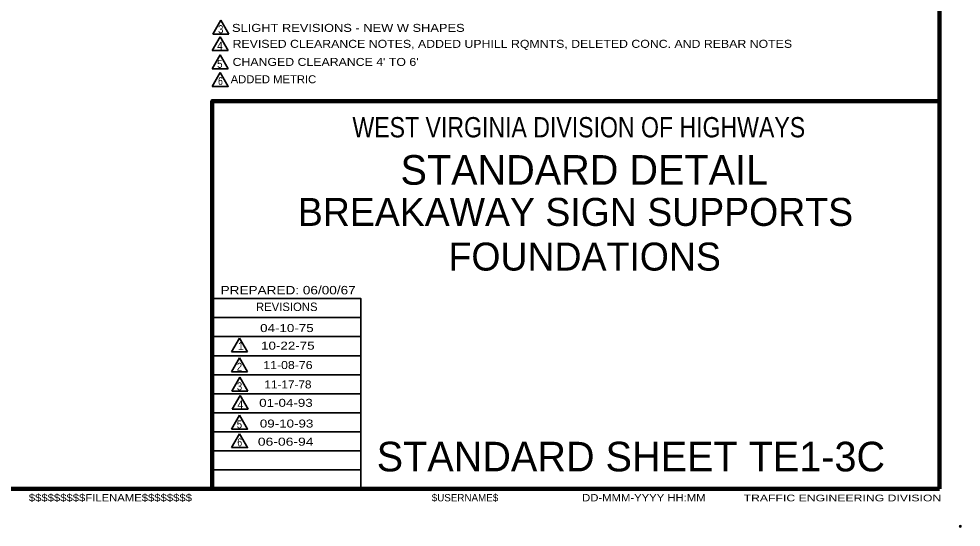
# Model space of a CAD drawing. Extents: x -27 to 828, y -12 to 532.
# Drawn here: x 546 to 828.5, y -12.5 to 140 of the extents above; entities that cross this region are included whole.
import ezdxf
from ezdxf.enums import TextEntityAlignment as Align

# ---------------------------------------------------------------- set-up
doc = ezdxf.new("R2010")
doc.units = 0
doc.header["$LTSCALE"] = 0.96
doc.header["$PDMODE"] = 32
doc.header["$PDSIZE"] = 0.48
doc.layers.add('1', color=7, linetype='Continuous', lineweight=35)
doc.layers.add('61', color=7, linetype='Continuous', lineweight=35)

msp = doc.modelspace()

# ---------------------------------------------------------------- linework, layer by layer
at = {"layer": '1', "lineweight": 158}
for q in [(821.9567, 525.1688), (821.9567, 115.3688), (30.3567, -0.9312)]:
    msp.add_line((821.9567, -0.9312), q, dxfattribs=at)
at = {"layer": '1', "lineweight": 13}
msp.add_line((821.9567, -0.9312), (821.9567, 525.1688), dxfattribs=at)
at = {"layer": '1'}
for p, q in [((606.5687, 139.616), (604.1687, 135.4591)), ((606.5687, 139.616), (608.9687, 135.4591)), ((606.2927, 134.647), (603.8927, 130.4901)), ((608.9687, 135.4591), (604.1687, 135.4591)), ((606.2927, 134.647), (608.6927, 130.4901)), ((608.6927, 130.4901), (603.8927, 130.4901)), ((606.2927, 129.2165), (603.8927, 125.0596)), ((606.2927, 129.2165), (608.6927, 125.0596)), ((608.6927, 125.0596), (603.8927, 125.0596)), ((606.375, 123.9367), (603.975, 119.7798)), ((648.4567, 50.4688), (603.9567, 50.4688)), ((648.4567, 44.7688), (603.9567, 44.7688)), ((612.1272, 44.2559), (609.7272, 40.099)), ((612.1272, 44.2559), (614.5272, 40.099)), ((614.5272, 40.099), (609.7272, 40.099)), ((648.4567, 38.9688), (603.9567, 38.9688)), ((612.1359, 38.2862), (609.7359, 34.1293)), ((612.1359, 38.2862), (614.5359, 34.1293)), ((614.5359, 34.1293), (609.7359, 34.1293)), ((648.4567, 33.2688), (603.9567, 33.2688)), ((612.1817, 32.5223), (609.7817, 28.3654)), ((612.1817, 32.5223), (614.5817, 28.3654)), ((614.5817, 28.3654), (609.7817, 28.3654)), ((648.4567, 27.5688), (603.9567, 27.5688)), ((612.3714, 27.0673), (609.9714, 22.9104)), ((612.3714, 27.0673), (614.7714, 22.9104)), ((614.7714, 22.9104), (609.9714, 22.9104)), ((648.4567, 21.8688), (603.9567, 21.8688)), ((612.1536, 21.107), (609.7536, 16.9501)), ((648.4567, 16.1688), (603.9567, 16.1688)), ((612.158, 15.5394), (609.758, 11.3825)), ((648.4567, 10.4688), (603.9567, 10.4688)), ((648.4567, 4.7688), (603.9567, 4.7688))]:
    msp.add_line(p, q, dxfattribs=at)
for points in [[(606.375, 123.9367), (608.775, 119.7798), (603.975, 119.7798)], [(648.4567, -0.9312), (648.4567, 56.1688), (603.9567, 56.1688)], [(612.1536, 21.107), (614.5536, 16.9501), (609.7536, 16.9501)], [(612.158, 15.5394), (614.558, 11.3825), (609.758, 11.3825)]]:
    msp.add_lwpolyline(points, dxfattribs=at)
at = {"layer": '1', "lineweight": 158}
msp.add_lwpolyline([(603.9567, -0.9312), (603.9567, 115.3688), (821.9567, 115.3688)], dxfattribs=at)
at = {"layer": '1'}
msp.add_point((828.2567, -12.2312), dxfattribs=at)
at = {"layer": '61', "lineweight": 53}
for q in [(669.2567, -0.9312), (669.2567, -0.9312), (669.2567, -0.9312), (669.5567, -0.9312), (669.5567, -0.9312)]:
    msp.add_line((821.9567, -0.9312), q, dxfattribs=at)

# ---------------------------------------------------------------- texts
at = {"layer": '1'}
for s, height, width, p in [('SLIGHT REVISIONS - NEW W SHAPES', 2.4, 1.2, (609.869, 136.1179)), ('3', 2.4, 0.9, (605.6919, 135.7262)), ('4', 2.4, 0.95, (605.4159, 130.7572)), ('REVISED CLEARANCE NOTES, ADDED UPHILL RQMNTS, DELETED CONC. AND REBAR NOTES', 2.4, 1.15, (610.053, 131.3329)), ('5', 2.4, 0.9, (605.4159, 125.3267)), ("CHANGED CLEARANCE 4' TO 6'", 2.4, 1.15, (610.053, 125.9024)), ('6', 2.4, 0.8, (605.6938, 120.1803)), ('ADDED METRIC', 2.4, 1.05, (609.4783, 120.7023)), ('PREPARED: 06/00/67', 2.537, 1.2, (606.4567, 57.3688)), ('2', 2.4, 0.9, (611.3114, 34.4598)), ('3', 2.4, 0.9, (611.3342, 28.5961)), ('4', 2.4, 0.95, (611.5239, 23.1411)), ('5', 2.4, 0.9, (611.3061, 17.1808)), ('6', 2.4, 0.8, (611.4768, 11.783)), ('$$$$$$$$$FILENAME$$$$$$$$', 2.2, 1.15, (548.9567, -4.7312)), ('DD-MMM-YYYY HH:MM', 2.2, 1.15, (714.8567, -4.7312)), ('TRAFFIC ENGINEERING DIVISION', 2.031, 1.35, (763.2567, -4.7312))]:
    msp.add_text(s, height=height, dxfattribs=dict(at, width=width)).set_placement(p)
for s, height, width, p in [('WEST VIRGINIA DIVISION OF HIGHWAYS', 6.089, 0.85, (713.8567, 104.4688)), ('04-10-75', 2.4, 1.25, (626.3344, 46.0596)), ('10-22-75', 2.4, 1.25, (626.6159, 40.7795)), ('11-08-76', 2.4, 1.15, (626.64, 34.9645)), ('11-17-78', 2.4, 1.1, (626.6399, 29.1495)), ('01-04-93', 2.4, 1.25, (626.0512, 23.6295)), ('09-10-93', 2.4, 1.25, (626.2432, 17.4127)), ('06-06-94', 2.4, 1.3, (625.9702, 11.9691))]:
    msp.add_text(s, height=height, dxfattribs=dict(at, width=width)).set_placement(p, align=Align.CENTER)
for s, height, p in [('STANDARD DETAIL', 8.881, (715.5067, 90.2688)), ('BREAKAWAY SIGN SUPPORTS', 8.391, (712.8662, 77.9108)), ('FOUNDATIONS', 8.391, (715.6239, 64.5116))]:
    msp.add_text(s, height=height, dxfattribs=at).set_placement(p, align=Align.CENTER)
for s, height, p in [('REVISIONS', 2.537, (617.0567, 52.3688)), ('1', 2.4, (611.6315, 40.6666)), ('STANDARD SHEET TE1-3C', 8.881, (653.2567, 4.2688)), ('$USERNAME$', 2.2, (669.7567, -4.7312))]:
    msp.add_text(s, height=height, dxfattribs=at).set_placement(p)

doc.saveas('drawing.dxf')
